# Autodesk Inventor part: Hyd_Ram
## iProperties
Company: Autodesk, Inc.
Created: 2004-06
Part Number: Hyd_Ram
Document SubType Name: Modeling
Designer: Autodesk
Manufacturer: Standard
Standards Organization: Custom
Density: 1 g/cm^3
Author: Autodesk, Inc.
Subject: Autodesk Inventor
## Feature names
1. Extrusion2
2. Mirror1
3. Extrusion3
4. Extrusion4
